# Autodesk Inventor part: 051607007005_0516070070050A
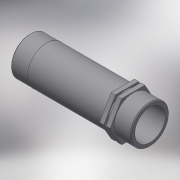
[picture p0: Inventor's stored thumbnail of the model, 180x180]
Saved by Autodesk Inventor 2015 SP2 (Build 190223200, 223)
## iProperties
Created: 2017-05
Part Number: 051607007005_0516070070050A
Material: Generic
Description: PLASSON RISER 3/4"-1/2"
Document SubType Name: Modeling
Designer: KIM
Mass: 20.3153 g
Surface Area: 184.457 cm^2
Volume: 20.3153 cm^3
Density: 1 g/cm^3
Appearance: Default
Author: KIM
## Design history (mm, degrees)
derived "051607.ipt"
feature "Solid1::051607.ipt"
tag "TaggingFeature1"
body "Solid1"
other parameters: "d1" = 26.441, "d2" = 27, "d3" = 21.1528, "d5" = 18, "d6" = 4.5, "d8" = 0.9, "d12" = 0, "d13" = 2.25, "d15" = 18, "d17" = 0, "d18" = 26.441, "R_" = 26.441, "E_" = 27, "l_2" = 18, "R_1" = 26.441
